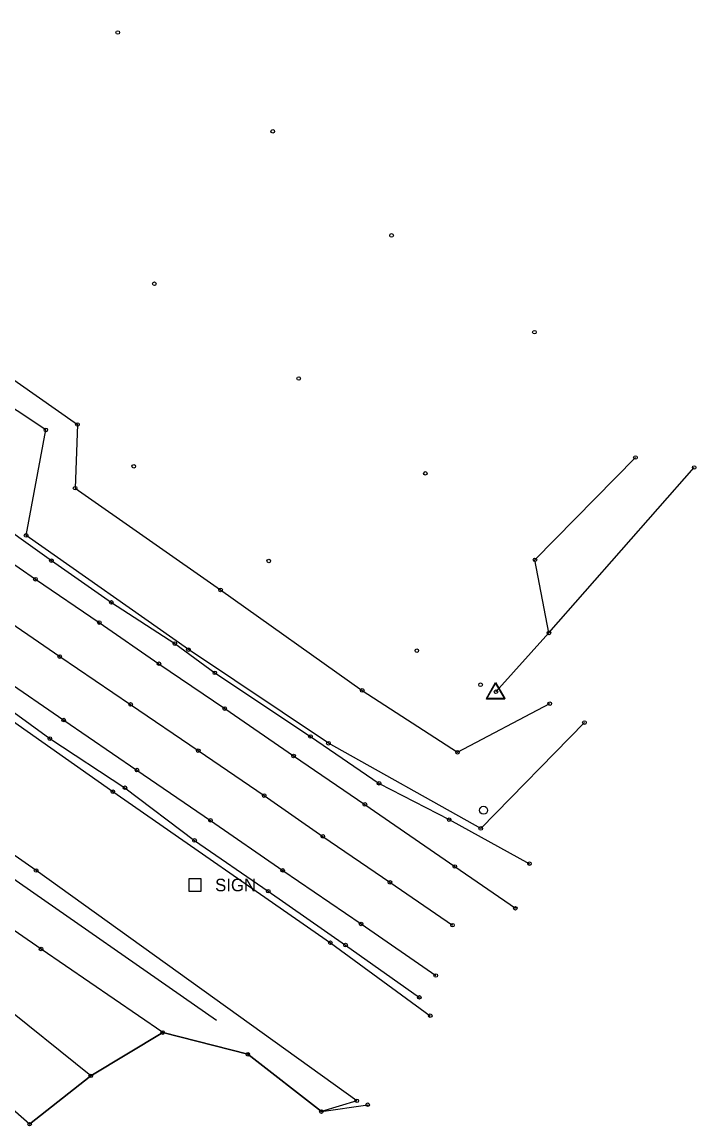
# Model space of a CAD drawing. Extents: x 15502398 to 15534190, y 8766930 to 8782112.
# Drawn here: x 15515143.1 to 15515330.8, y 8778822.3 to 8779129.6 of the extents above; entities that cross this region are included whole.
import ezdxf

# ---------------------------------------------------------------- set-up
doc = ezdxf.new("R2010")
doc.units = 0
for name, color, linetype in [('EXT_BL', 7, 'Continuous'), ('EXT_C', 7, 'Continuous'), ('EXT_D', 7, 'Continuous'), ('EXT_EP', 7, 'Continuous'), ('EXT_SNP', 7, 'Continuous'), ('Fence', 7, 'Continuous'), ('Natural', 7, 'Continuous'), ('SurControl', 7, 'Continuous'), ('SurPointsNonDTM', 7, 'Continuous'), ('SurRoadPoints', 7, 'Continuous'), ('SurSurveyPoints', 7, 'Continuous')]:
    doc.layers.add(name, color=color, linetype=linetype)

msp = doc.modelspace()

# ---------------------------------------------------------------- linework, layer by layer
at = {"layer": 'EXT_BL'}
for points in [[(15514972.37, 8779103.34), (15514965.29, 8779104.12), (15514949.73, 8779114.8), (15514960.51, 8779127.28), (15514971.69, 8779129.58), (15515012.98, 8779104.1), (15515039.09, 8779087.26), (15515084.34, 8779057.54), (15515121.87, 8779031.85), (15515136.34, 8779033.05), (15515158.53, 8779017.54), (15515157.87, 8778999.81), (15515198.39, 8778971.5), (15515237.86, 8778943.51), (15515264.4, 8778926.3), (15515290.1, 8778939.84)], [(15515299.76, 8778934.56), (15515270.88, 8778905.08), (15515228.44, 8778928.8), (15515189.45, 8778954.86), (15515144.22, 8778986.67), (15515149.73, 8779016.04), (15515133.63, 8779026.63), (15515113.74, 8779009.34), (15515065.03, 8779042.26), (15515052.77, 8779057.78), (15515036.39, 8779065.61), (15515003.2, 8779083.25), (15514972.37, 8779103.34)], [(15515236.34, 8778829.26), (15515147, 8778893.37), (15515095.71, 8778929.07), (15515036.69, 8778970.82), (15514983.06, 8779009.89), (15514945.58, 8779038.12), (15514929.61, 8779051.74), (15514918.26, 8779072.09), (15514924.14, 8779086.4)], [(15514924.14, 8779086.4), (15514944.89, 8779074.69), (15514948.37, 8779068.62), (15514949.86, 8779067.79), (15514955.86, 8779058.94), (15515004.6, 8779026.01), (15515051.74, 8778995.2), (15515103.32, 8778961.08), (15515168.39, 8778915.33), (15515228.98, 8778873.25), (15515256.8, 8778852.96)], [(15515182.28, 8778848.25), (15515148.4, 8778871.52), (15515131.84, 8778882.87), (15515120.14, 8778892.33), (15515119.53, 8778897.92), (15515112.5, 8778902.46), (15515101.01, 8778904.62), (15515092.27, 8778909.96), (15515052.18, 8778939.84), (15515012.09, 8778969.72), (15514972.2, 8778999.45)], [(15515162.24, 8778836.22), (15515136.09, 8778857.21), (15515107.41, 8778878.44), (15515081.62, 8778898.18), (15515041, 8778927.34), (15515000.39, 8778956.51), (15514958.68, 8778986.46)], [(15515236.34, 8778829.26), (15515226.47, 8778826.26), (15515206, 8778842.2), (15515182.28, 8778848.25), (15515162.24, 8778836.22), (15515145.2, 8778822.76), (15515124.7, 8778840.65), (15515095.48, 8778865.85), (15515068.16, 8778888.68), (15515024.46, 8778912.95), (15514980.75, 8778937.23), (15514934.3, 8778963.03)]]:
    msp.add_lwpolyline(points, dxfattribs=at)
at = {"layer": 'EXT_C'}
msp.add_lwpolyline([(15514955.43, 8779089.67), (15514965.34, 8779083.38), (15514972.98, 8779078.29), (15514981.11, 8779072.17), (15514988.29, 8779067.21), (15514995.56, 8779062.44), (15514996.44, 8779061.55), (15515003.11, 8779056.73), (15515023.53, 8779042.6), (15515042.26, 8779029.68), (15515060.1, 8779017.29), (15515079.18, 8779004.26), (15515097.5, 8778991.51), (15515115.64, 8778978.97), (15515133.93, 8778966.45), (15515153.59, 8778952.94), (15515173.34, 8778939.62), (15515192.18, 8778926.74), (15515210.55, 8778914.23), (15515226.89, 8778902.88), (15515245.57, 8778890.09), (15515263, 8778878.15)], dxfattribs=at)
at = {"layer": 'EXT_D'}
msp.add_line((15515197.28, 8778851.57), (15514927.71, 8779039.18), dxfattribs=at)
at = {"layer": 'EXT_EP'}
for points in [[(15515004, 8779071.19), (15515021.39, 8779058.52), (15515036.5, 8779048.12), (15515053.54, 8779036.32), (15515073.21, 8779022.82), (15515093.16, 8779009.36), (15515104.5, 8779002.14), (15515104.91, 8779002.59), (15515122.29, 8778991.19), (15515128.53, 8778987.1), (15515146.83, 8778974.46), (15515164.62, 8778962.4), (15515181.23, 8778950.95), (15515199.54, 8778938.45), (15515218.74, 8778925.26), (15515238.6, 8778911.77), (15515263.66, 8778894.48), (15515280.51, 8778882.85)], [(15514989.57, 8779051.49), (15514997.49, 8779045.8), (15515004.92, 8779040.68), (15515013.98, 8779034.36), (15515029.92, 8779023.61), (15515039.85, 8779016.64), (15515057.6, 8779004.48), (15515078.3, 8778990.12), (15515099.03, 8778975.76), (15515113.27, 8778966.3), (15515112.33, 8778964.28), (15515131.99, 8778950.83), (15515154.7, 8778935.27), (15515175.1, 8778921.33), (15515195.6, 8778907.33), (15515215.71, 8778893.41), (15515237.55, 8778878.49), (15515258.35, 8778864.15)]]:
    msp.add_lwpolyline(points, dxfattribs=at)
at = {"layer": 'EXT_SNP'}
for points in [[(15515058.99, 8779041.35), (15515076.89, 8779030.08), (15515098.01, 8779015.66), (15515109.36, 8779008.51), (15515127.95, 8778995.86), (15515132.65, 8778992.91), (15515151.28, 8778979.64), (15515167.98, 8778968), (15515185.66, 8778956.55), (15515196.8, 8778948.4), (15515223.42, 8778930.68), (15515242.55, 8778917.64), (15515262.08, 8778907.53), (15515284.46, 8778895.27)], [(15515031.37, 8779018.91), (15515039.75, 8779010.04), (15515053.15, 8778998.58), (15515073.46, 8778983.69), (15515095.02, 8778968.8), (15515109.51, 8778959.31), (15515128.81, 8778946.07), (15515150.83, 8778930.1), (15515171.77, 8778916.42), (15515191.15, 8778901.74), (15515211.68, 8778887.62), (15515233.22, 8778872.61), (15515253.77, 8778858.06)]]:
    msp.add_lwpolyline(points, dxfattribs=at)
at = {"layer": 'Fence'}
msp.add_lwpolyline([(15515275.11, 8778943.14), (15515289.85, 8778959.51), (15515330.32, 8779005.58)], dxfattribs=at)
at = {"layer": 'Natural'}
for points in [[(15515289.87, 8778959.5), (15515285.98, 8778979.86), (15515313.96, 8779008.36)], [(15515145.2, 8778822.76), (15515162.24, 8778836.22), (15515182.28, 8778848.25), (15515206, 8778842.2), (15515226.47, 8778826.26), (15515239.39, 8778828.18)]]:
    msp.add_lwpolyline(points, dxfattribs=at)
at = {"layer": 'SurControl'}
for points in [[(15515274.99, 8778945.69), (15515277.54, 8778941.28), (15515272.44, 8778941.28)], [(15515275.01, 8778945.44), (15515277.55, 8778941.04), (15515272.46, 8778941.04)]]:
    msp.add_lwpolyline(points, close=True, dxfattribs=at)
msp.add_circle((15515271.65, 8778910.15), 1.12, dxfattribs=at)
at = {"layer": 'SurPointsNonDTM'}
for centre in [(15515313.96, 8779008.36), (15515330.32, 8779005.58), (15515285.98, 8778979.86), (15515289.85, 8778959.51), (15515289.87, 8778959.5), (15515275.11, 8778943.14), (15515182.28, 8778848.25), (15515206, 8778842.2), (15515162.24, 8778836.22), (15515226.47, 8778826.26), (15515239.39, 8778828.18), (15515145.2, 8778822.76)]:
    msp.add_circle(centre, 0.5, dxfattribs=at)
at = {"layer": 'SurRoadPoints'}
msp.add_lwpolyline([(15515191.26, 8778887.63), (15515191.26, 8778887.63), (15515192.97, 8778887.63), (15515192.97, 8778891.06), (15515189.55, 8778891.06), (15515189.55, 8778887.63), (15515191.26, 8778887.63)], dxfattribs=at)
at = {"layer": 'SurSurveyPoints'}
for centre in [(15515169.76, 8779126.68), (15515212.94, 8779099.15), (15515246.03, 8779070.18), (15515179.95, 8779056.73), (15515285.82, 8779043.26), (15515220.16, 8779030.36), (15515158.53, 8779017.54), (15515149.73, 8779016.04), (15515174.21, 8779005.91), (15515255.42, 8779003.94), (15515157.87, 8778999.81), (15515144.22, 8778986.67), (15515151.28, 8778979.64), (15515211.83, 8778979.56), (15515146.83, 8778974.46), (15515198.39, 8778971.5), (15515167.98, 8778968), (15515164.62, 8778962.4), (15515185.66, 8778956.55), (15515153.59, 8778952.94), (15515189.45, 8778954.86), (15515253.07, 8778954.58), (15515181.23, 8778950.95), (15515196.8, 8778948.4), (15515237.86, 8778943.51), (15515270.83, 8778945.09), (15515173.34, 8778939.62), (15515290.1, 8778939.84), (15515199.54, 8778938.45), (15515154.7, 8778935.27), (15515299.76, 8778934.56), (15515223.42, 8778930.68), (15515150.83, 8778930.1), (15515228.44, 8778928.8), (15515192.18, 8778926.74), (15515218.74, 8778925.26), (15515264.4, 8778926.3), (15515175.1, 8778921.33), (15515168.39, 8778915.33), (15515171.77, 8778916.42), (15515242.55, 8778917.64), (15515210.55, 8778914.23), (15515238.6, 8778911.77), (15515195.6, 8778907.33), (15515262.08, 8778907.53), (15515226.89, 8778902.88), (15515270.88, 8778905.08), (15515191.15, 8778901.74), (15515263.66, 8778894.48), (15515284.46, 8778895.27), (15515147, 8778893.37), (15515215.71, 8778893.41), (15515211.68, 8778887.62), (15515245.57, 8778890.09), (15515280.51, 8778882.85), (15515237.55, 8778878.49), (15515263, 8778878.15), (15515228.98, 8778873.25), (15515233.22, 8778872.61), (15515148.4, 8778871.52), (15515258.35, 8778864.15), (15515253.77, 8778858.06), (15515256.8, 8778852.96), (15515182.28, 8778848.25), (15515182.28, 8778848.25), (15515206, 8778842.2), (15515162.24, 8778836.22), (15515162.24, 8778836.22), (15515236.34, 8778829.26), (15515236.34, 8778829.26), (15515226.47, 8778826.26), (15515145.2, 8778822.76)]:
    msp.add_circle(centre, 0.5, dxfattribs=at)

# ---------------------------------------------------------------- texts
at = {"layer": 'SurRoadPoints'}
msp.add_text('SIGN', height=3.498, dxfattribs=at).set_placement((15515196.87, 8778887.59))

doc.saveas('drawing.dxf')
